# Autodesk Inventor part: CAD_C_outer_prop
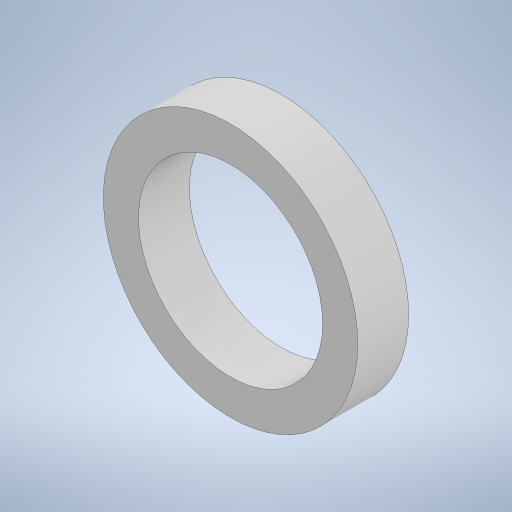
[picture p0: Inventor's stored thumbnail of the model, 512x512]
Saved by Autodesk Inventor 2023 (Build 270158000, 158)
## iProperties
Created: 2023-05
Part Number: CAD_C_outer_prop
Material: Generic
Document SubType Name: Modeling
Designer: steff
Density: 1 g/cm^3
Appearance: Default
Author: steff
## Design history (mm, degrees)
sketch "Sketch1"
  geometry: C1 r 9.05 at (0, 0); C2 r 12.5 at (0, 0); 1 further point
  constraints: 2 centre point, 2 coincident
  dimensions: "d0" = 18.1 diameter of C1; "d1" = 25 diameter of C2
extrude "Extrusion1" new body sketch "Sketch1" distance "d2" = 5; taper "d3" = 0 deg
body "Solid1"
